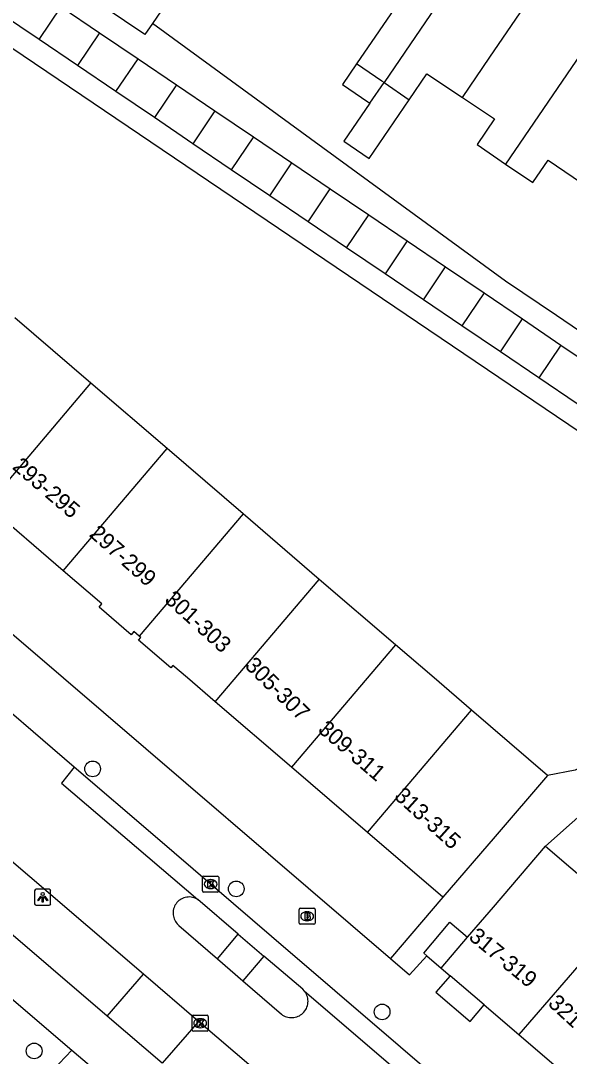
# Model space of a CAD drawing. Extents: x 159280 to 160375, y 384531 to 385872.
# Drawn here: x 159850.6 to 159884.8, y 384726.4 to 384790.9 of the extents above; entities that cross this region are included whole.
import ezdxf

# ---------------------------------------------------------------- set-up
doc = ezdxf.new("R2010")
doc.units = 0
for name, color, linetype in [('IMGEO_Boom', 7, 'Continuous'), ('IMGEO_Brandkraan', 7, 'Continuous'), ('IMGEO_Fietspad_open', 7, 'Continuous'), ('IMGEO_Kolk', 7, 'Continuous'), ('IMGEO_Lichtpunt', 7, 'Continuous'), ('IMGEO_Pand', 7, 'Continuous'), ('IMGEO_Pand_nummerreeks', 7, 'Continuous'), ('IMGEO_Rijbaan_lokaal_open', 7, 'Continuous'), ('IMGEO_Voetpad_halfverhard', 7, 'Continuous'), ('IMGEO_Voetpad_open', 7, 'Continuous')]:
    doc.layers.add(name, color=color, linetype=linetype)

msp = doc.modelspace()

# ---------------------------------------------------------------- linework, layer by layer
at = {"layer": 'IMGEO_Boom'}
for centre in [(159855.08, 384744.341), (159864.023, 384736.87), (159873.107, 384729.208), (159851.438, 384726.777)]:
    msp.add_circle(centre, 0.489, dxfattribs=at)
at = {"layer": 'IMGEO_Brandkraan'}
for p, q in [((159868.011, 384735.665), (159868.863, 384735.665)), ((159867.936, 384734.739), (159867.936, 384735.591)), ((159868.424, 384735.445), (159868.449, 384735.445)), ((159868.937, 384735.591), (159868.937, 384734.739)), ((159868.863, 384734.665), (159868.011, 384734.665)), ((159868.447, 384734.885), (159868.422, 384734.885))]:
    msp.add_line(p, q, dxfattribs=at)
for points in [[(159868.011, 384735.665), (159868.863, 384735.665)], [(159867.936, 384734.739), (159867.936, 384735.591)], [(159868.284, 384735.365), (159868.284, 384734.965), (159868.497, 384734.965)], [(159868.515, 384735.365), (159868.284, 384735.365)], [(159868.463, 384735.284), (159868.409, 384735.284), (159868.409, 384735.208)], [(159868.409, 384735.208), (159868.462, 384735.208)], [(159868.471, 384735.132), (159868.409, 384735.132), (159868.409, 384735.051)], [(159868.409, 384735.051), (159868.471, 384735.051)], [(159868.937, 384735.591), (159868.937, 384734.739)], [(159868.863, 384734.665), (159868.011, 384734.665)]]:
    msp.add_lwpolyline(points, dxfattribs=at)
for centre, radius, start, end in [((159868.013, 384735.589), 0.0765, 91.55205, 178.44795), ((159868.013, 384735.589), 0.0765, 91.55205, 178.44795), ((159868.861, 384735.589), 0.0765, 1.55205, 88.44795), ((159868.861, 384735.589), 0.0765, 1.55205, 88.44795), ((159868.464, 384735.246), 0.0379, 267.82845, 90.93552), ((159868.472, 384735.091), 0.0404, 269.87594, 90.50774), ((159868.519, 384735.22), 0.145, 59.4692, 91.53667), ((159868.544, 384735.267), 0.0922, 285.51372, 58.15012), ((159868.549, 384735.075), 0.105, 301.31148, 78.98903), ((159868.013, 384734.741), 0.0765, 181.55205, 268.44795), ((159868.013, 384734.741), 0.0765, 181.55205, 268.44795), ((159868.503, 384735.216), 0.251, 268.66757, 293.53466), ((159868.861, 384734.741), 0.0765, 271.55205, 358.44795), ((159868.861, 384734.741), 0.0765, 271.55205, 358.44795)]:
    msp.add_arc(centre, radius, start, end, dxfattribs=at)
for centre, major_axis, ratio, start_param, end_param in [((159868.423, 384735.165), (-0.387, 0.002), 0.722429, 4.712389, 7.853982), ((159868.448, 384735.165), (-0.39, 0.002), 0.717154, 1.570796, 4.712389)]:
    msp.add_ellipse(centre, major_axis=major_axis, ratio=ratio, start_param=start_param, end_param=end_param, dxfattribs=at)
at = {"layer": 'IMGEO_Fietspad_open'}
for points in [[(159855.982, 384728.954), (159831.413, 384750), (159802.682, 384774.612), (159803.886, 384778.134)], [(159801.703, 384771.392), (159826.697, 384750), (159853.776, 384726.823)], [(159859.416, 384726.013), (159855.982, 384728.954)], [(159853.776, 384726.823), (159857.499, 384723.68)]]:
    msp.add_lwpolyline(points, dxfattribs=at)
at = {"layer": 'IMGEO_Kolk'}
for p, q in [((159861.928, 384736.743), (159861.928, 384737.595)), ((159862.003, 384737.669), (159862.855, 384737.669)), ((159862.929, 384737.595), (159862.929, 384736.743)), ((159862.416, 384737.449), (159862.441, 384737.449)), ((159862.855, 384736.669), (159862.003, 384736.669)), ((159862.439, 384736.889), (159862.414, 384736.889)), ((159861.278, 384728.08), (159861.278, 384728.932)), ((159861.353, 384729.006), (159862.205, 384729.006)), ((159861.766, 384728.786), (159861.791, 384728.786)), ((159862.279, 384728.932), (159862.279, 384728.08)), ((159862.205, 384728.006), (159861.353, 384728.006)), ((159861.789, 384728.226), (159861.764, 384728.226))]:
    msp.add_line(p, q, dxfattribs=at)
for points in [[(159861.928, 384736.743), (159861.928, 384737.595)], [(159862.003, 384737.669), (159862.855, 384737.669)], [(159862.929, 384737.595), (159862.929, 384736.743)], [(159862.249, 384737.369), (159862.372, 384737.369), (159862.372, 384737.218), (159862.502, 384737.369), (159862.666, 384737.369), (159862.52, 384737.218), (159862.673, 384736.969), (159862.521, 384736.969), (159862.436, 384737.133), (159862.372, 384737.066), (159862.372, 384736.969), (159862.249, 384736.969), (159862.249, 384737.369)], [(159862.855, 384736.669), (159862.003, 384736.669)], [(159861.278, 384728.08), (159861.278, 384728.932)], [(159861.353, 384729.006), (159862.205, 384729.006)], [(159861.599, 384728.706), (159861.722, 384728.706), (159861.722, 384728.555), (159861.852, 384728.706), (159862.016, 384728.706), (159861.87, 384728.555), (159862.023, 384728.306), (159861.871, 384728.306), (159861.786, 384728.47), (159861.722, 384728.403), (159861.722, 384728.306), (159861.599, 384728.306), (159861.599, 384728.706)], [(159862.279, 384728.932), (159862.279, 384728.08)], [(159862.205, 384728.006), (159861.353, 384728.006)]]:
    msp.add_lwpolyline(points, dxfattribs=at)
for centre, start, end in [((159862.005, 384737.593), 91.55205, 178.44795), ((159862.005, 384737.593), 91.55205, 178.44795), ((159862.853, 384737.593), 1.55205, 88.44795), ((159862.853, 384737.593), 1.55205, 88.44795), ((159862.005, 384736.745), 181.55205, 268.44795), ((159862.005, 384736.745), 181.55205, 268.44795), ((159862.853, 384736.745), 271.55205, 358.44795), ((159862.853, 384736.745), 271.55205, 358.44795), ((159861.355, 384728.93), 91.55205, 178.44795), ((159861.355, 384728.93), 91.55205, 178.44795), ((159862.203, 384728.93), 1.55205, 88.44795), ((159862.203, 384728.93), 1.55205, 88.44795), ((159861.355, 384728.082), 181.55205, 268.44795), ((159861.355, 384728.082), 181.55205, 268.44795), ((159862.203, 384728.082), 271.55205, 358.44795), ((159862.203, 384728.082), 271.55205, 358.44795)]:
    msp.add_arc(centre, 0.0765, start, end, dxfattribs=at)
for centre, major_axis, ratio, start_param, end_param in [((159862.415, 384737.169), (-0.387, 0.002), 0.722429, 4.712389, 7.853982), ((159862.44, 384737.169), (-0.39, 0.002), 0.717154, 1.570796, 4.712389), ((159861.765, 384728.506), (-0.387, 0.002), 0.722429, 4.712389, 7.853982), ((159861.79, 384728.506), (-0.39, 0.002), 0.717154, 1.570796, 4.712389)]:
    msp.add_ellipse(centre, major_axis=major_axis, ratio=ratio, start_param=start_param, end_param=end_param, dxfattribs=at)
at = {"layer": 'IMGEO_Lichtpunt'}
for p, q in [((159851.47, 384736.752), (159851.47, 384735.945)), ((159851.47, 384736.752), (159851.47, 384735.945)), ((159852.372, 384736.847), (159851.564, 384736.847)), ((159852.372, 384736.847), (159851.564, 384736.847)), ((159852.466, 384735.945), (159852.466, 384736.752)), ((159852.466, 384735.945), (159852.466, 384736.752)), ((159851.564, 384735.851), (159852.372, 384735.851)), ((159851.564, 384735.851), (159852.372, 384735.851))]:
    msp.add_line(p, q, dxfattribs=at)
for points in [[(159851.844, 384736.416), (159851.883, 384736.388), (159851.695, 384736.126), (159851.657, 384736.153), (159851.844, 384736.416)], [(159851.946, 384736.368), (159851.993, 384736.368), (159851.993, 384736.046), (159851.946, 384736.046), (159851.946, 384736.368)], [(159852.056, 384736.388), (159852.094, 384736.415), (159852.281, 384736.153), (159852.242, 384736.125), (159852.056, 384736.388)]]:
    msp.add_lwpolyline(points, dxfattribs=at)
msp.add_circle((159851.969, 384736.55), 0.0994, dxfattribs=at)
for centre, start, end in [((159851.564, 384736.752), 90, 180), ((159851.564, 384736.752), 90, 180), ((159852.372, 384736.752), 0, 90), ((159852.372, 384736.752), 0, 90), ((159851.564, 384735.945), 180, 270), ((159851.564, 384735.945), 180, 270), ((159852.372, 384735.945), 270, 0), ((159852.372, 384735.945), 270, 360)]:
    msp.add_arc(centre, 0.0946, start, end, dxfattribs=at)
at = {"layer": 'IMGEO_Pand'}
for points in [[(159880.295, 384797.458), (159873.225, 384787.078)], [(159878.115, 384786.14), (159879.822, 384788.664), (159884.398, 384795.384)], [(159854.541, 384792.641), (159856.097, 384794.927), (159859.885, 384792.347), (159858.8, 384790.754)], [(159872.274, 384793.782), (159874.333, 384792.38), (159871.515, 384788.242)], [(159858.8, 384790.754), (159858.329, 384790.062), (159854.541, 384792.641)], [(159851.742, 384789.746), (159853.12, 384791.784)], [(159853.12, 384791.784), (159855.514, 384790.164)], [(159887.847, 384792.347), (159880.797, 384781.995)], [(159851.742, 384789.746), (159849.349, 384791.366)], [(159855.514, 384790.164), (159854.136, 384788.127)], [(159855.514, 384790.164), (159857.908, 384788.545)], [(159854.136, 384788.127), (159851.742, 384789.746)], [(159856.53, 384786.508), (159857.908, 384788.545)], [(159857.908, 384788.545), (159860.302, 384786.926)], [(159856.53, 384786.508), (159854.136, 384788.127)], [(159871.515, 384788.242), (159870.636, 384786.951), (159872.214, 384785.877), (159872.346, 384785.787)], [(159873.225, 384787.078), (159873.093, 384787.167), (159871.515, 384788.242)], [(159874.799, 384786.006), (159875.897, 384787.618), (159878.115, 384786.14)], [(159860.302, 384786.926), (159858.924, 384784.889)], [(159860.302, 384786.926), (159862.695, 384785.307)], [(159872.346, 384785.787), (159873.225, 384787.078)], [(159873.225, 384787.078), (159874.799, 384786.006)], [(159858.924, 384784.889), (159856.53, 384786.508)], [(159872.346, 384785.787), (159870.732, 384783.418), (159872.307, 384782.346), (159874.799, 384786.006)], [(159878.115, 384786.14), (159880.107, 384784.813), (159879.015, 384783.209), (159880.797, 384781.995)], [(159862.695, 384785.307), (159861.317, 384783.269)], [(159862.695, 384785.307), (159865.089, 384783.687)], [(159861.317, 384783.269), (159858.924, 384784.889)], [(159865.089, 384783.687), (159863.711, 384781.65)], [(159865.089, 384783.687), (159867.483, 384782.068)], [(159863.711, 384781.65), (159861.317, 384783.269)], [(159866.105, 384780.031), (159867.483, 384782.068)], [(159867.483, 384782.068), (159869.877, 384780.449)], [(159880.797, 384781.995), (159882.488, 384780.844), (159883.44, 384782.242), (159885.518, 384780.826)], [(159866.105, 384780.031), (159863.711, 384781.65)], [(159868.499, 384778.412), (159869.877, 384780.449)], [(159869.877, 384780.449), (159872.271, 384778.83)], [(159868.499, 384778.412), (159866.105, 384780.031)], [(159870.892, 384776.792), (159868.499, 384778.412)], [(159870.892, 384776.792), (159872.271, 384778.83)], [(159872.271, 384778.83), (159874.664, 384777.21)], [(159874.664, 384777.21), (159873.286, 384775.173)], [(159874.664, 384777.21), (159877.058, 384775.591)], [(159873.286, 384775.173), (159870.892, 384776.792)], [(159875.68, 384773.554), (159873.286, 384775.173)], [(159875.68, 384773.554), (159877.058, 384775.591)], [(159877.058, 384775.591), (159879.452, 384773.972)], [(159879.452, 384773.972), (159878.074, 384771.935)], [(159879.452, 384773.972), (159881.846, 384772.353)], [(159878.074, 384771.935), (159875.68, 384773.554)], [(159854.972, 384768.352), (159850.232, 384772.422)], [(159880.468, 384770.315), (159878.074, 384771.935)], [(159880.468, 384770.315), (159881.846, 384772.353)], [(159881.846, 384772.353), (159884.239, 384770.733)], [(159884.239, 384770.733), (159882.861, 384768.696)], [(159884.239, 384770.733), (159886.633, 384769.114)], [(159882.861, 384768.696), (159880.468, 384770.315)], [(159885.255, 384767.077), (159882.861, 384768.696)], [(159848.505, 384760.744), (159854.972, 384768.352)], [(159859.712, 384764.282), (159854.972, 384768.352)], [(159853.245, 384756.674), (159859.712, 384764.282)], [(159864.451, 384760.212), (159859.712, 384764.282)], [(159853.245, 384756.674), (159848.505, 384760.744)], [(159864.451, 384760.212), (159857.987, 384752.607)], [(159869.191, 384756.142), (159864.451, 384760.212)], [(159857.987, 384752.607), (159857.652, 384752.895), (159857.482, 384752.697), (159855.482, 384754.414), (159855.65, 384754.609), (159853.245, 384756.674)], [(159862.714, 384748.522), (159869.191, 384756.142)], [(159873.931, 384752.073), (159869.191, 384756.142)], [(159862.714, 384748.522), (159860.993, 384750), (159860.08, 384750.784), (159859.941, 384750.623), (159857.93, 384752.35), (159858.081, 384752.526), (159857.987, 384752.607)], [(159873.931, 384752.073), (159867.454, 384744.452)], [(159878.671, 384748.003), (159876.345, 384750), (159873.931, 384752.073)], [(159867.454, 384744.452), (159862.714, 384748.522)], [(159872.194, 384740.382), (159878.671, 384748.003)], [(159883.411, 384743.933), (159878.671, 384748.003)], [(159872.194, 384740.382), (159867.454, 384744.452)], [(159883.411, 384743.933), (159880.153, 384740.14), (159876.895, 384736.346)], [(159876.895, 384736.346), (159872.194, 384740.382)], [(159878.428, 384733.857), (159880.036, 384735.734), (159883.289, 384739.531)], [(159883.289, 384739.531), (159888.15, 384735.367)], [(159888.15, 384735.367), (159881.618, 384727.795)], [(159876.783, 384731.936), (159878.428, 384733.857)], [(159876.783, 384731.936), (159877.337, 384731.462)], [(159879.464, 384729.64), (159877.337, 384731.462)], [(159879.464, 384729.64), (159881.618, 384727.795)], [(159881.618, 384727.795), (159883.819, 384725.91)]]:
    msp.add_lwpolyline(points, dxfattribs=at)
at = {"layer": 'IMGEO_Rijbaan_lokaal_open'}
for points in [[(159853.929, 384744.456), (159847.45, 384750), (159836.494, 384759.376), (159815.158, 384777.694), (159809.818, 384782.351)], [(159858.25, 384731.558), (159847.676, 384740.593), (159836.596, 384750), (159834.815, 384751.53), (159822.73, 384761.9), (159811.286, 384771.727), (159808.08, 384774.505), (159805.152, 384776.974)], [(159853.929, 384744.456), (159853.146, 384743.458), (159861.625, 384736.208)], [(159878.198, 384723.622), (159866.219, 384733.909), (159858.974, 384740.138), (159853.929, 384744.456)], [(159861.625, 384736.208), (159861.547, 384736.253), (159861.466, 384736.29), (159861.382, 384736.32), (159861.295, 384736.342), (159861.207, 384736.357), (159861.117, 384736.364), (159861.028, 384736.362), (159860.939, 384736.353), (159860.851, 384736.335), (159860.765, 384736.31), (159860.682, 384736.278), (159860.601, 384736.238), (159860.525, 384736.191), (159860.454, 384736.137), (159860.387, 384736.077), (159860.326, 384736.012), (159860.271, 384735.941), (159860.223, 384735.866), (159860.181, 384735.786), (159860.147, 384735.704), (159860.12, 384735.618), (159860.101, 384735.531), (159860.09, 384735.442), (159860.087, 384735.352), (159860.092, 384735.263), (159860.105, 384735.174), (159860.126, 384735.087), (159860.154, 384735.002), (159860.19, 384734.92), (159860.233, 384734.842), (159860.283, 384734.767), (159860.339, 384734.698), (159860.402, 384734.634), (159860.443, 384734.597), (159862.847, 384732.518)], [(159864.146, 384734.051), (159861.625, 384736.208)], [(159864.146, 384734.051), (159865.74, 384732.675)], [(159862.847, 384732.518), (159864.435, 384731.14)], [(159868.281, 384730.496), (159868.165, 384730.624), (159865.74, 384732.675)], [(159861.667, 384728.607), (159858.25, 384731.558)], [(159864.435, 384731.14), (159866.835, 384729.069), (159866.909, 384729.016), (159866.988, 384728.969), (159867.071, 384728.93), (159867.157, 384728.898), (159867.245, 384728.874), (159867.335, 384728.859), (159867.427, 384728.851), (159867.518, 384728.851), (159867.609, 384728.86), (159867.699, 384728.876), (159867.788, 384728.901), (159867.873, 384728.934), (159867.956, 384728.974), (159868.034, 384729.021), (159868.108, 384729.075), (159868.177, 384729.135), (159868.24, 384729.201), (159868.297, 384729.273), (159868.347, 384729.349), (159868.391, 384729.43), (159868.427, 384729.514), (159868.455, 384729.601), (159868.475, 384729.691), (159868.488, 384729.781), (159868.492, 384729.873), (159868.488, 384729.964), (159868.476, 384730.055), (159868.455, 384730.144), (159868.427, 384730.231), (159868.391, 384730.316), (159868.348, 384730.396), (159868.298, 384730.473), (159868.281, 384730.496)], [(159868.281, 384730.496), (159877.401, 384722.674), (159878.198, 384723.622)], [(159884.673, 384708.967), (159884.588, 384709.04), (159883.518, 384709.956), (159861.667, 384728.607)]]:
    msp.add_lwpolyline(points, dxfattribs=at)
at = {"layer": 'IMGEO_Voetpad_halfverhard'}
msp.add_lwpolyline([(159853.776, 384726.823), (159851.029, 384723.93), (159848.632, 384726.205), (159825.6, 384745.284), (159805.116, 384763.503), (159800.659, 384767.301), (159801.703, 384771.392)], dxfattribs=at)
at = {"layer": 'IMGEO_Voetpad_open'}
for points in [[(159822.578, 384807.809), (159896.975, 384757.494), (159896.887, 384757.365), (159889.352, 384746.225), (159885.124, 384744.266), (159883.411, 384743.933)], [(159896.056, 384764.329), (159883.963, 384772.562), (159880.797, 384774.717), (159858.8, 384790.754)], [(159808.268, 384788.603), (159853.266, 384750), (159873.623, 384732.536)], [(159883.289, 384739.531), (159888.262, 384743.946), (159918.005, 384724.436)], [(159876.895, 384736.346), (159873.623, 384732.536)], [(159875.896, 384732.709), (159875.705, 384732.876), (159877.324, 384734.798), (159878.428, 384733.857)], [(159862.847, 384732.518), (159864.146, 384734.051)], [(159865.74, 384732.675), (159864.435, 384731.14)], [(159873.623, 384732.536), (159874.812, 384731.516), (159875.896, 384732.709)], [(159875.896, 384732.709), (159876.783, 384731.936)], [(159855.982, 384728.954), (159858.25, 384731.558)], [(159877.337, 384731.462), (159876.458, 384730.434), (159878.584, 384728.613), (159879.464, 384729.64)], [(159861.667, 384728.607), (159859.416, 384726.013)]]:
    msp.add_lwpolyline(points, dxfattribs=at)

# ---------------------------------------------------------------- texts
at = {"layer": 'IMGEO_Pand_nummerreeks'}
for s, rotation, p in [('293-295', 319.40021, (159850.024, 384763.067)), ('297-299', 318.48348, (159854.809, 384758.878)), ('301-303', 317.86468, (159859.499, 384754.795)), ('305-307', 315.48118, (159864.503, 384750.699)), ('309-311', 319.40021, (159869.047, 384746.698)), ('313-315', 317.86468, (159873.804, 384742.556)), ('317-319', 320.52894, (159878.44, 384733.774)), ('321-323', 317.49226, (159883.379, 384729.659))]:
    msp.add_text(s, height=1, rotation=rotation, dxfattribs=at).set_placement(p)

doc.saveas('drawing.dxf')
